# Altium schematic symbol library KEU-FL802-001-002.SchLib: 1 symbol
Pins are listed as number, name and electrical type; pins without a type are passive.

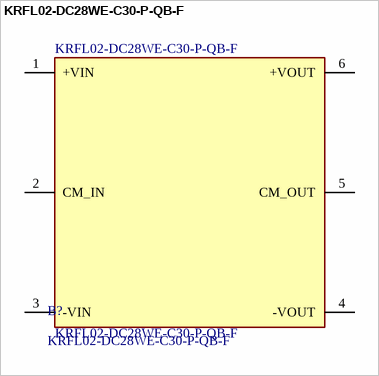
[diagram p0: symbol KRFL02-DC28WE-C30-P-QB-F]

## KRFL02-DC28WE-C30-P-QB-F
designator B?
30Aout Passive Quarter EMI Filter Brick with Flanged Option; MFG: KOLT
footprint KRFL02-DC28WE-C30-P-QB-F
pins: 1 +VIN, 2 CM_IN, 3 -VIN, 4 -VOUT, 5 CM_OUT, 6 +VOUT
